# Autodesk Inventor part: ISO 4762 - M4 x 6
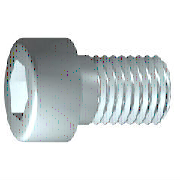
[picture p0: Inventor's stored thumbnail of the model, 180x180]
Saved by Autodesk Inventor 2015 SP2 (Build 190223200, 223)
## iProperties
IsCustomPart: 0
Created: 2014-02
Part Number: ISO 4762 - M4 x 6
Material: Edelstahl, 440C
Description: Innensechskantschraube
Document SubType Name: Modeling
Standard: ISO 4762
Designer: rYan
Standard Revision: Fourth edition 2004-03-01
Standards Organization: ISO
Language: de-DE
Size Designation: M4 x 6
Categories: <MemberInstance><Categories><Category DisplayName="Verbindungselemente" InternalName="e4da775c-781d-43d5-af7c-5136215cf5a6" Mnemonic="FSTN"><Category DisplayNam
Density: 7.75 g/cm^3
Appearance: Halbpoliert
Author: rYan
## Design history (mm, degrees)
sketch "Skizze1"
  geometry: L1 (-1, 0)-(4, 0); L2 (4, 0)-(4, 2); L3 (4, 2)-(0.75, 2); L4 (0.75, 2)-(0.32, 2); L5 (0.32, 2)-(0, 2); L6 (0, 2)-(0, 3.5); L7 (0, 3.5)-(-4, 3.5); L8 (-4, 3.5)-(-4, 1.732); L9 (-4, 1.732)-(-2, 1.732); L10 (-2, 1.732)-(-1, 0); L11 (-6, 0)-(8, 0) reference; L12 (0, -0.7)-(0, 4.2) reference; L13 (0.75, 2)-(0, 2)
  constraints: 22 end point, 6 parallel, 2 collinear, 2 perpendicular, 1 horizontal, 1 point on line
  dimensions: "d1" = 3.25 distance from line of L3.end L2 (= GEL); "d2" = 0.42952 distance of L4.end L3.end (computed from GAL); "d3" = 4 distance between parallel lines of L8 L6 (= KOH); "d4" = 2 distance of L8.end L9.end (= INTI); "d5" = 60 deg angle of L10 L1; "d6" = 4 diameter of L3 L1 (= GD); "d7" = 4 diameter of L5 L1 (= BDM); "d8" = 3.4641 diameter of L9 L1 (= 1.1547 x SW); "d9" = 7 diameter of L7 L1 (= KOD); "d26" = 4 distance between parallel lines of L12 L2 (= NLG)
revolve "Körper" sketch "Skizze1" stored, may be unused: angle "d10" = 90 deg
sketch "Skizze2"
  geometry: L1 (0, -4.9)-(0, 4.9) reference; L2 (-4.9, 0)-(4.9, 0) reference; L3 (1.732, 0)-(0.866, -1.5); L4 (0.866, -1.5)-(-0.866, -1.5); L5 (-0.866, -1.5)-(-1.732, 0); L6 (-1.732, 0)-(-0.866, 1.5); L7 (-0.866, 1.5)-(0.866, 1.5); L8 (0.866, 1.5)-(1.732, 0); 2 further points
  constraints: 12 end point, 1 coincident, 1 horizontal alignment, 1 point on line, 12 other
extrude "Loch" join sketch "Skizze2" stored distance "d11" = 10; taper "d12" = 0 deg
workplane "Work Plane1"
fillet "Fillet2" dims "d30" = 0.1 (= R)
body "Solid1"
fillet "Rundung1" dims "d17" = 0.4 (= RR)
feature "Gewinde" dims "d13" = 3.25 (= GEL), "d14" = 0
chamfer "Fase1" distance "d15" = 0.42941 (= -0.5 x SPD + 0.5 x GD); stored, may be unused: second distance "d16" = 0.42941 (= GUL), angle "d27" = 45 deg
other parameters: "GD" = 4 [user parameter; used in 2 equation terms], "NLG" = 4 [user parameter; used in 1 equation term], "GEL" = 3.25 [user parameter; used in 2 equation terms], "KOD" = 7 [user parameter; used in 1 equation term], "KOH" = 4 [user parameter; used in 1 equation term], "INTI" = 2 [user parameter; used in 1 equation term], "GAL" = 0.42941 (= 0.61345 x PTC) [user parameter; used in 1 equation term], "GUL" = 0.42941 (= 0.61345 x PTC) [user parameter; used in 1 equation term], "BDM" = 4 (= NND) [user parameter; used in 1 equation term], "SW" = 3 [user parameter; used in 2 equation terms], "RR" = 0.4 [user parameter; used in 1 equation term], "SPD" = 3.14117 (= NND - 1.2269 x PTC) [user parameter; used in 1 equation term], "d19" = 0, "d28" = 0, "d29" = 0, "R" = 0.1 [user parameter; used in 1 equation term], "TOA" = 30 deg [user parameter], "GD1" = 3.14117 (= THREADDIA - 1.2269 x PTC) [user parameter], "THREADDIA" = 4 [user parameter; used in 1 equation term], "FAWI" = 45 deg [user parameter], "TPU" = 14.28571 (computed from PTC) [user parameter], "PTC" = 0.7 [user parameter; used in 5 equation terms], "NND" = 4 [user parameter; used in 2 equation terms], "E0" = 3.465 (= 1.155 x SW) [user parameter]
